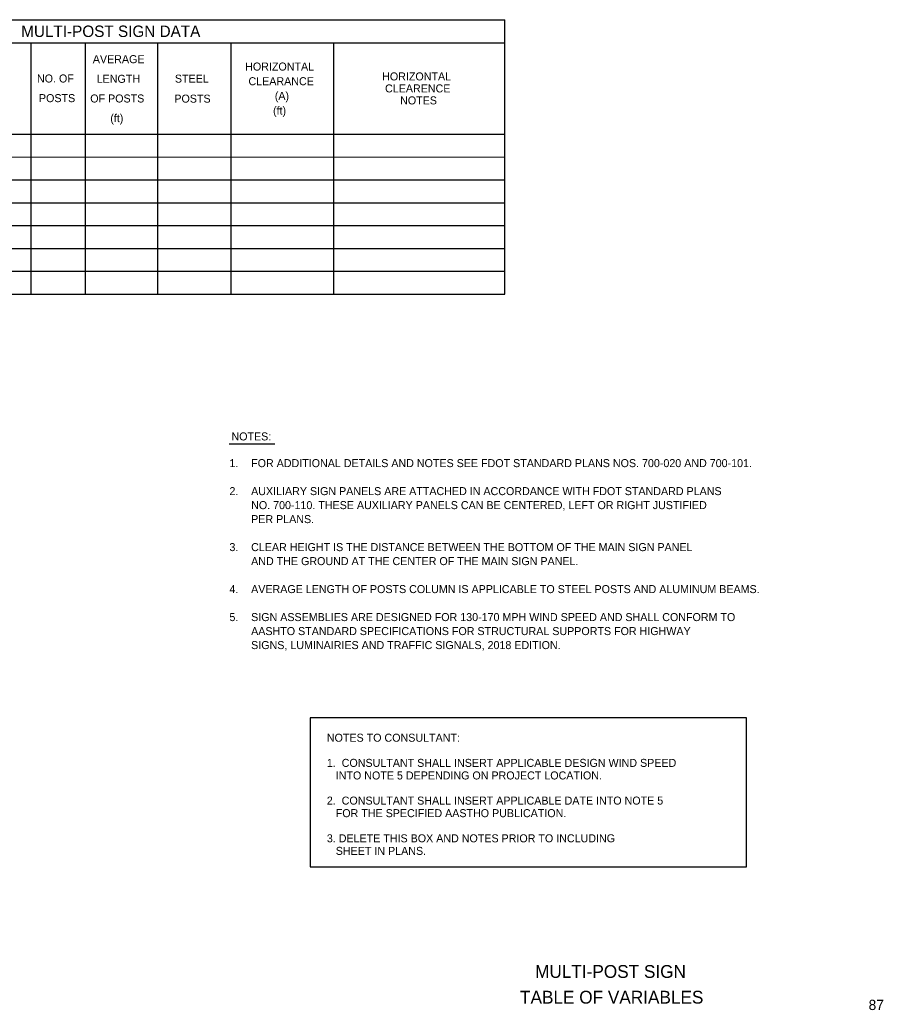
# Model space of a CAD drawing. Extents: x 10268865 to 10269006, y 2142584 to 2142673.
# Drawn here: x 10268930.5 to 10269006.1, y 2142586.2 to 2142672.9 of the extents above; entities that cross this region are included whole.
import ezdxf

# ---------------------------------------------------------------- set-up
doc = ezdxf.new("R2010")
doc.units = 0
for name, color, linetype in [('TextAlert', 7, 'Continuous'), ('TextMisc', 7, 'Continuous'), ('TextNotes', 7, 'Continuous'), ('TextShtNo', 7, 'Continuous'), ('TextTables', 7, 'Continuous')]:
    doc.layers.add(name, color=color, linetype=linetype)

msp = doc.modelspace()

# ---------------------------------------------------------------- linework, layer by layer
at = {"layer": 'TextAlert'}
msp.add_lwpolyline([(10268955.931, 2142598.743), (10268994.137, 2142598.743), (10268994.137, 2142611.778), (10268955.931, 2142611.778)], close=True, dxfattribs=at)
at = {"layer": 'TextNotes'}
msp.add_line((10268948.828, 2142635.752), (10268952.832, 2142635.752), dxfattribs=at)
at = {"layer": 'TextTables'}
for p, q in [((10268905.887, 2142672.868), (10268972.968, 2142672.872)), ((10268972.972, 2142648.864), (10268972.968, 2142672.873)), ((10268905.888, 2142670.867), (10268972.969, 2142670.871)), ((10268931.46, 2142670.866), (10268931.464, 2142648.857)), ((10268936.218, 2142670.869), (10268936.221, 2142648.858)), ((10268942.561, 2142670.868), (10268942.565, 2142648.859)), ((10268948.985, 2142670.863), (10268948.988, 2142648.86)), ((10268957.954, 2142670.863), (10268957.957, 2142648.861)), ((10268905.889, 2142662.863), (10268972.97, 2142662.867)), ((10268905.889, 2142660.864), (10268972.97, 2142660.867)), ((10268905.89, 2142658.863), (10268972.971, 2142658.867)), ((10268905.89, 2142656.863), (10268972.971, 2142656.867)), ((10268905.89, 2142654.862), (10268972.971, 2142654.866)), ((10268905.891, 2142652.862), (10268972.972, 2142652.865)), ((10268905.891, 2142650.861), (10268972.972, 2142650.865)), ((10268905.891, 2142648.86), (10268972.972, 2142648.864))]:
    msp.add_line(p, q, dxfattribs=at)

# ---------------------------------------------------------------- texts
at = {"layer": 'TextAlert'}
for s, p in [('NOTES TO CONSULTANT:', (10268957.381, 2142609.69)), ('1.  CONSULTANT SHALL INSERT APPLICABLE DESIGN WIND SPEED', (10268957.381, 2142607.489)), ('   INTO NOTE 5 DEPENDING ON PROJECT LOCATION.', (10268957.381, 2142606.389)), ('2.  CONSULTANT SHALL INSERT APPLICABLE DATE INTO NOTE 5', (10268957.381, 2142604.188)), ('   FOR THE SPECIFIED AASTHO PUBLICATION.', (10268957.381, 2142603.088)), ('3. DELETE THIS BOX AND NOTES PRIOR TO INCLUDING ', (10268957.381, 2142600.887)), ('   SHEET IN PLANS.', (10268957.381, 2142599.787))]:
    msp.add_text(s, height=0.70025, dxfattribs=at).set_placement(p)
at = {"layer": 'TextMisc'}
for s, p in [('    MULTI-POST SIGN     ', (10268973.944, 2142589.019)), ('   TABLE OF VARIABLES   ', (10268973.044, 2142586.769))]:
    msp.add_text(s, height=1.125, rotation=360, dxfattribs=at).set_placement(p)
at = {"layer": 'TextNotes'}
for s, height, p in [('NOTES:', 0.7002, (10268949.029, 2142636.061)), ('1. ', 0.7, (10268948.851, 2142633.723)), ('FOR ADDITIONAL DETAILS AND NOTES SEE FDOT STANDARD PLANS NOS. 700-020 AND 700-101.', 0.7, (10268950.752, 2142633.723)), ('2. ', 0.7, (10268948.851, 2142631.273)), ('AUXILIARY SIGN PANELS ARE ATTACHED IN ACCORDANCE WITH FDOT STANDARD PLANS', 0.7, (10268950.752, 2142631.273)), ('NO. 700-110. THESE AUXILIARY PANELS CAN BE CENTERED, LEFT OR RIGHT JUSTIFIED', 0.7, (10268950.752, 2142630.048)), ('PER PLANS.', 0.7, (10268950.752, 2142628.823)), ('3. ', 0.7, (10268948.851, 2142626.373)), ('CLEAR HEIGHT IS THE DISTANCE BETWEEN THE BOTTOM OF THE MAIN SIGN PANEL', 0.7, (10268950.752, 2142626.373)), ('AND THE GROUND AT THE CENTER OF THE MAIN SIGN PANEL.', 0.7, (10268950.752, 2142625.148)), ('4. ', 0.7, (10268948.851, 2142622.698)), ('AVERAGE LENGTH OF POSTS COLUMN IS APPLICABLE TO STEEL POSTS AND ALUMINUM BEAMS. ', 0.7, (10268950.752, 2142622.698)), ('5. ', 0.7, (10268948.851, 2142620.248)), ('SIGN ASSEMBLIES ARE DESIGNED FOR 130-170 MPH WIND SPEED AND SHALL CONFORM TO', 0.7, (10268950.752, 2142620.248)), ('AASHTO STANDARD SPECIFICATIONS FOR STRUCTURAL SUPPORTS FOR HIGHWAY', 0.7, (10268950.752, 2142619.023)), ('SIGNS, LUMINAIRIES AND TRAFFIC SIGNALS, 2018 EDITION. ', 0.7, (10268950.752, 2142617.798))]:
    msp.add_text(s, height=height, dxfattribs=at).set_placement(p)
at = {"layer": 'TextShtNo'}
msp.add_text('87', height=0.9, rotation=360, dxfattribs=at).set_placement((10269004.817, 2142586.207))
at = {"layer": 'TextTables'}
for s, height, p in [('MULTI-POST SIGN DATA', 1.00036, (10268930.621, 2142671.368)), ('AVERAGE', 0.7003, (10268936.888, 2142669.077)), ('HORIZONTAL', 0.7003, (10268950.23, 2142668.431)), ('NO. OF', 0.7003, (10268932.001, 2142667.386)), ('STEEL', 0.7003, (10268944.076, 2142667.375)), ('HORIZONTAL', 0.7003, (10268962.223, 2142667.568)), ('LENGTH', 0.7003, (10268937.226, 2142667.357)), ('CLEARANCE', 0.7003, (10268950.519, 2142667.147)), ('CLEARENCE', 0.7003, (10268962.477, 2142666.518)), ('POSTS', 0.7003, (10268932.173, 2142665.666)), ('OF POSTS', 0.7003, (10268936.664, 2142665.637)), ('(A)', 0.7003, (10268952.824, 2142665.863)), ('POSTS', 0.7003, (10268944.03, 2142665.624)), ('NOTES', 0.7003, (10268963.797, 2142665.468)), ('(ft)', 0.7003, (10268938.421, 2142663.917)), ('(ft)', 0.7003, (10268952.67, 2142664.579))]:
    msp.add_text(s, height=height, rotation=0.0098, dxfattribs=at).set_placement(p)

doc.saveas('drawing.dxf')
